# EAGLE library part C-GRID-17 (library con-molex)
CONNECTOR wire to board 2.54 mm (0.100") pitch header
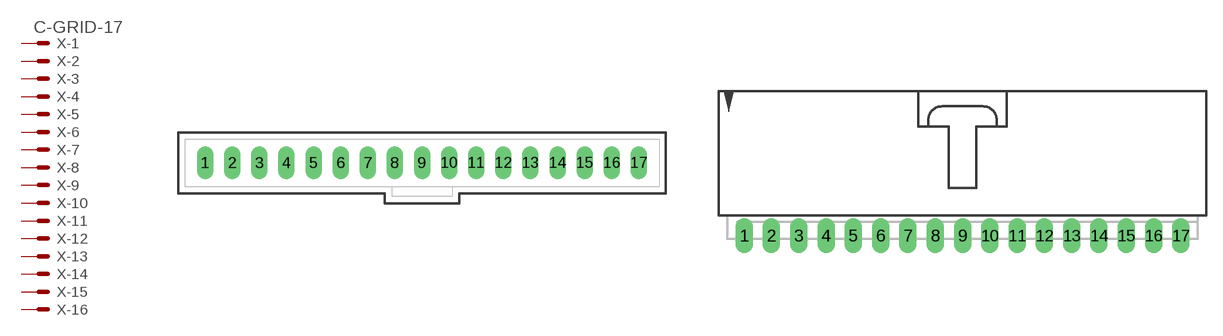
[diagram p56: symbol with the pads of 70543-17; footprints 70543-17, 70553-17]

Designator prefix X; gates -1=MV -2=M -3=M -4=M -5=M -6=M -7=M -8=M -9=M -10=M -11=M -12=M -13=M -14=M -15=M -16=M -17=M

## C-GRID-17-70543 (OC_FARNELL: unknown; OC_NEWARK: unknown)  [70543-17]
1  -1:S  pas
2  -2:S  pas
3  -3:S  pas
4  -4:S  pas
5  -5:S  pas
6  -6:S  pas
7  -7:S  pas
8  -8:S  pas
9  -9:S  pas
10  -10:S  pas
11  -11:S  pas
12  -12:S  pas
13  -13:S  pas
14  -14:S  pas
15  -15:S  pas
16  -16:S  pas
17  -17:S  pas

## C-GRID-17-70553 (OC_FARNELL: unknown; OC_NEWARK: unknown)  [70553-17]
Pads as for 70543-17

## Footprint 70543-17 (pad centres in mm)
C-Grid SL Connector vertical, 17 pin
drill 1.016 long: 1 -20.32,0; 2 -17.78,0; 3 -15.24,0; 4 -12.7,0; 5 -10.16,0; 6 -7.62,0; 7 -5.08,0; 8 -2.54,0; 9 0,0; 10 2.54,0; 11 5.08,0; 12 7.62,0; 13 10.16,0; 14 12.7,0; 15 15.24,0; 16 17.78,0; 17 20.32,0

## Footprint 70553-17 (pad centres in mm)
C-Grid SL Connector right angle, 17 pin
drill 1.092 long: 1 -20.32,-7.62; 2 -17.78,-7.62; 3 -15.24,-7.62; 4 -12.7,-7.62; 5 -10.16,-7.62; 6 -7.62,-7.62; 7 -5.08,-7.62; 8 -2.54,-7.62; 9 0,-7.62; 10 2.54,-7.62; 11 5.08,-7.62; 12 7.62,-7.62; 13 10.16,-7.62; 14 12.7,-7.62; 15 15.24,-7.62; 16 17.78,-7.62; 17 20.32,-7.62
